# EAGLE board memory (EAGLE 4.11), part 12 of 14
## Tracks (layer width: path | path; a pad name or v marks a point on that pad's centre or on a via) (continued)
N$318  (via drill 0.61) (continued)
  Top 0.254: F14.S2 334.64,21.59 333.38,20.32 333.38,14.61 332.11,13.34 F14.V2 332.11,12.06 v332.11,9.52 | F09.P2 398.78,27.94 400.05,26.67 400.05,17.78 398.78,16.51 F09.U2 398.14,15.24 v398.14,9.52 400.69,6.98 400.69,1.27 460.38,1.27 v460.38,3.81 | v452.75,158.11 454.02,159.38 454.02,162.56 450.85,165.73 450.85,172.09 447.68,175.26 447.68,188.59 448.94,189.86 D05.E2 449.58,191.13 450.85,192.41 v450.85,211.45 | v446.4,147.32 447.04,146.69 447.04,134.62 447.68,133.99 447.68,90.8 v452.75,85.72 | v466.73,80.64 v466.73,54.61 466.73,45.72 472.44,45.72 473.07,45.09 473.07,42.55 469.9,39.37 469.9,10.16 v462.92,3.17 | v79.38,276.86 79.38,340.36 80.01,341 80.01,357.5 80.64,358.14 A34.U2 | v154.94,274.32 155.57,273.69 155.57,227.97 158.75,224.79 158.75,217.81 v164.47,212.09 | v223.52,215.26 v223.52,211.45
  Route2 0.254: v460.38,3.81 461.01,3.17 v462.92,3.17
  Bottom 0.254: F09.N2 395.61,31.12 397.51,29.21 398.14,29.21 F09.P2 | v332.11,9.52 370.84,9.52 371.48,10.16 397.51,10.16 v398.14,9.52 | v452.75,158.11 451.49,156.84 445.13,156.84 444.5,156.21 444.5,147.32 v446.4,147.32 | v452.75,85.72 457.83,80.64 v466.73,80.64 | v466.73,54.61 462.28,54.61 F04.E2 | v79.38,276.86 80.01,277.5 137.16,277.5 139.7,274.96 149.22,274.96 149.86,275.59 153.67,275.59 v154.94,274.32 | v164.47,212.09 165.1,212.72 175.26,212.72 175.9,213.36 205.1,213.36 207.01,211.45 v223.52,211.45 | v223.52,215.26 224.16,214.63 316.87,214.63 317.5,215.26 329.56,215.26 330.83,214 342.9,214 344.81,212.09 381,212.09 381.63,212.72 386.71,212.72 388.62,210.82 431.17,210.82 431.8,211.45 v450.85,211.45
N$319
  Route3 0.254: D05.D2 446.4,193.04 446.4,189.23 447.68,187.96 447.68,151.76 454.02,145.41 454.02,121.92 455.3,120.65 455.3,119.38 454.02,118.11 454.02,45.09 458.47,40.64 458.47,38.73 F04.L2
N$320
  Bottom 0.254: F09.M2 398.78,34.92 402.59,34.92 404.5,33.02 413.38,33.02 414.02,33.66 416.56,33.66 429.89,20.32 434.34,20.32 436.25,18.41 436.25,16.51 F06.U2
N$321
  Bottom 0.254: A12.S2 360.68,364.49 361.31,363.86 365.76,363.86 367.03,362.59 369.57,362.59 A11.T2
N$322  (via drill 0.61)
  Top 0.254: v439.42,189.23 441.32,191.13 441.32,206.38 439.42,208.28 439.42,217.17 438.15,218.44 438.15,227.33 439.42,228.6 v439.42,229.87 | v417.83,236.85 417.19,237.49 417.19,239.39 415.93,240.66 415.93,250.82 v417.19,252.09 | v414.65,313.06 413.38,314.33 413.38,316.23 412.75,316.87 412.75,324.49 414.02,325.75 v414.02,327.66 | v400.05,341.63 v405.13,336.55 | v373.38,342.27 373.38,358.14 A11.U2 | v273.05,417.2 273.05,398.78 271.78,397.51 A19.E2
  Route2 0.254: v405.13,336.55 v414.02,327.66
  Route3 0.254: v439.42,189.23 438.15,187.96 438.15,160.66 436.88,159.38 D06.S2 | v417.19,252.09 415.93,253.36 415.93,311.79 v414.65,313.06 | v365.76,415.29 365.12,414.66 365.12,403.86 361.95,400.69 361.95,386.08 374.65,373.38 374.65,360.68 373.38,359.41 A11.U2
  Bottom 0.254: v439.42,229.87 436.25,233.04 427.99,233.04 424.81,236.22 418.46,236.22 v417.83,236.85 | v400.05,341.63 387.99,341.63 387.35,342.27 v373.38,342.27 | v273.05,417.2 306.07,417.2 307.34,415.93 318.13,415.93 320.04,414.02 328.3,414.02 330.2,415.93 365.12,415.93 v365.76,415.29
N$323  (via drill 0.61)
  Top 0.254: v485.77,149.86 485.77,93.98 487.05,92.71 E02.S2
  Bottom 0.254: v485.77,149.86 485.14,150.5 478.79,150.5 474.35,154.94 471.81,154.94 D03.T2
N$326  (via drill 0.61)
  Top 0.254: v382.9,53.98 382.9,56.52 F10.D2
  Bottom 0.254: v382.9,53.98 384.18,55.25 386.71,55.25 389.89,52.07 392.43,52.07 393.06,52.7 401.95,52.7 402.59,52.07 411.48,52.07 415.29,55.88 417.83,55.88 418.46,55.25 427.36,55.25 427.99,55.88 430.53,55.88 431.17,55.25 440.06,55.25 440.69,55.88 443.23,55.88 443.87,55.25 452.75,55.25 453.39,55.88 455.93,55.88 456.56,55.25 465.45,55.25 466.09,55.88 468.63,55.88 469.26,55.25 473.71,55.25 474.35,54.61 F03.E2
N$327  (via drill 0.61)
  Top 0.254: v218.44,293.37 219.07,292.74 219.07,278.77 v224.16,273.69 | v274.32,271.78 274.95,272.42 274.95,278.13 v280.67,283.85 | v477.52,222.25 479.43,220.34 479.43,207.01 v480.06,206.38 | v494.03,109.22 492.76,107.95 492.76,106.04 492.12,105.41 492.12,50.16 v484.5,42.55
  Route2 0.254: v224.16,273.69 226.69,271.15 234.31,271.15 237.49,274.32 238.76,274.32 241.3,276.86 264.8,276.86 269.88,271.78 v274.32,271.78 | v280.67,283.85 281.94,282.58 287.65,282.58 288.93,283.85 311.15,283.85 313.69,281.31 320.04,281.31 321.94,283.21 367.03,283.21 367.67,283.85 368.3,283.85 369.57,282.58 392.43,282.58 394.33,284.48 396.24,284.48 396.88,285.12 400.05,285.12 408.94,276.23 417.83,276.23 434.98,259.08 441.96,259.08 442.6,258.44 448.31,258.44 v455.93,250.82 | v464.82,247.65 473.07,239.39 473.07,225.42 474.35,225.42 v477.52,222.25 | v480.06,206.38 494.67,191.77 501.01,191.77 501.65,191.13 501.65,187.32 500.38,186.06 500.38,185.42 501.01,185.42 501.65,184.78 501.65,131.44 502.92,131.44 504.19,130.18 504.19,128.91 502.92,128.91 495.3,121.28 495.3,109.22 v494.03,109.22
  Route3 0.254: v386.08,50.8 386.08,53.34 F10.E2
  Bottom 0.254: v386.08,50.8 386.08,48.9 387.35,48.9 390.52,45.72 400.69,45.72 401.32,46.36 403.86,46.36 405.13,45.09 407.67,45.09 F08.J2 408.31,45.09 410.21,46.99 410.85,46.99 F08.H2 411.48,46.99 412.12,46.36 416.56,46.36 417.19,45.72 426.08,45.72 426.72,46.36 429.26,46.36 433.07,42.55 441.96,42.55 442.6,43.18 451.49,43.18 452.12,42.55 454.66,42.55 455.3,43.18 464.19,43.18 464.82,42.55 467.36,42.55 468,43.18 476.25,43.18 480.69,38.73 | v218.44,293.37 214,293.37 213.36,294 208.91,294 208.28,294.64 B24.S2 | v455.93,250.82 457.2,252.09 460.38,252.09 v464.82,247.65 | 480.69,38.73 478.15,36.2 473.07,36.2 471.81,37.46 F03.L2 | 480.69,38.73 v484.5,42.55
N$328  (via drill 0.61)
  Top 0.254: v406.4,43.82 406.4,48.9 407.67,50.16 F08.F2
  Bottom 0.254: v406.4,43.82 407.04,43.18 413.38,43.18 414.02,42.55 416.56,42.55 417.19,43.18 426.08,43.18 426.72,42.55 429.26,42.55 429.89,43.18 431.17,43.18 432.44,41.91 436.25,41.91 F06.K2
N$329
  Bottom 0.254: E22.T2 230.5,88.27 232.41,86.36 233.04,86.36 E22.U2
N$330  (via drill 0.61)
  Top 0.254: B33.J2 90.17,318.14 90.17,323.22 B33.F2 | v209.55,320.68 v209.55,305.44
  Route2 0.254: v268.61,319.41 276.23,311.79 280.67,311.79 B18.L2 | B33.J2 90.81,316.87 90.81,313.06 99.06,313.06 105.41,306.71 111.76,306.71 115.57,302.9 124.46,302.9 128.27,306.71 137.16,306.71 140.97,302.9 147.32,302.9 150.5,299.72 157.48,299.72 161.29,303.53 172.09,303.53 172.72,302.9 175.26,302.9 179.07,306.71 187.96,306.71 188.59,306.07 197.49,306.07 198.12,306.71 200.66,306.71 201.93,305.44 204.47,305.44 B24.N2
  Bottom 0.254: v209.55,305.44 205.1,305.44 B24.N2 | v209.55,320.68 210.82,321.95 213.36,321.95 214,322.58 222.88,322.58 226.69,318.77 227.33,318.77 230.5,321.95 238.76,321.95 239.4,322.58 248.28,322.58 248.92,321.95 251.46,321.95 252.09,322.58 260.99,322.58 261.62,321.95 264.16,321.95 264.8,322.58 265.43,322.58 v268.61,319.41
N$331  (via drill 0.61)
  Top 0.254: v20.32,159.38 22.23,161.29 v22.23,180.34
  Bottom 0.254: v20.32,159.38 17.78,159.38 D39.S2 | v22.23,180.34 27.3,185.42 35.56,185.42 36.2,186.06 45.09,186.06 45.72,185.42 48.26,185.42 49.53,186.69 52.07,186.69 D36.F2
N$332
  Bottom 0.254: D39.N2 14.61,167.64 15.88,166.37 22.86,166.37 26.67,170.18 35.56,170.18 36.2,169.54 45.09,169.54 48.9,173.35 53.98,173.35 55.24,172.09 D36.M2
N$334  (via drill 0.61)
  Route3 0.254: v52.7,117.47 52.7,120.02 E36.F2
  Bottom 0.254: v52.7,117.47 55.24,117.47 E36.H2
OP1  (via drill 0.61)
  Top 0.254: v363.22,371.48 365.12,369.57 365.12,283.85 370.2,278.77 370.2,273.69 368.3,271.78 368.3,269.24 368.94,268.61 368.94,264.8 369.57,264.16 C11.D2 | B26.P2 182.88,302.26 183.51,302.9 183.51,306.71 184.15,307.34 184.15,325.12 182.88,326.39 B26.E2 | E13.R2 344.81,94.61 344.81,91.44 346.07,90.17 346.07,87.63 347.35,86.36 E13.U2 347.98,85.09 v347.98,73.02 | F17.K2 296.55,41.91 295.27,43.18 295.27,55.25 294,56.52 F17.D2 | v339.73,73.02 337.19,70.48 337.19,64.77 336.55,64.13 336.55,49.53 335.28,48.26 F14.H2 | v201.93,148.59 202.56,147.95 202.56,139.7 200.03,137.16 200.03,127.63 v205.1,122.55 | v368.3,237.49 368.3,220.98 363.22,215.9 363.22,201.93 361.95,200.66 361.95,189.23 v360.05,187.32
  Route2 0.254: v179.07,183.51 184.15,178.44 184.15,163.83 186.06,163.83 201.29,148.59 v201.93,148.59 | v205.1,122.55 206.38,121.28 206.38,116.2 211.46,116.2 217.81,109.85 226.06,109.85 229.87,106.04 234.31,106.04 238.12,102.23 238.12,95.25 v239.4,95.25 | v347.35,174.62 v360.05,187.32
  Route3 0.254: F14.D2 332.11,56.52 333.38,55.25 333.38,49.53 334.64,48.26 F14.H2 | v179.07,183.51 177.8,184.78 177.8,187.96 179.07,189.23 179.07,189.86 177.8,191.13 177.8,213.36 190.5,226.06 190.5,236.85 187.32,240.03 187.32,270.51 180.97,276.86 180.97,295.91 182.88,297.81 182.88,300.99 B26.P2 | v239.4,95.25 238.12,93.98 238.12,78.74 247.65,69.22 247.65,62.23 257.18,52.7 263.52,52.7 263.52,54.61 264.8,55.88 273.05,55.88 273.05,48.26 276.23,45.09 280.67,45.09 F18.J2 | v368.3,237.49 368.3,238.76 369.57,240.03 369.57,241.94 368.3,243.2 368.3,261.62 369.57,262.89 C11.D2 | v347.35,174.62 346.07,173.35 346.07,146.05 342.9,142.88 342.9,97.16 344.17,95.88 E13.R2
  Bottom 0.254: v363.22,371.48 360.68,371.48 A12.P2 | F18.J2 281.31,43.82 282.57,42.55 289.56,42.55 290.19,43.18 295.27,43.18 296.55,41.91 F17.K2 | F14.D2 331.47,57.15 327.66,57.15 325.75,59.05 316.87,59.05 316.23,58.42 313.69,58.42 313.06,59.05 304.17,59.05 303.53,58.42 300.99,58.42 300.36,59.05 295.27,59.05 294,57.79 F17.D2 | v347.98,73.02 v339.73,73.02
OP2  (via drill 0.61)
  Top 0.254: v282.57,3.81 282.57,26.03 281.31,27.3 281.31,31.12 F18.N2 | v396.88,3.17 396.88,20.32 398.14,21.59 F09.S2 | v320.68,280.67 320.68,286.39 319.4,287.66 319.4,291.47 B15.T2 | v252.09,281.94 248.92,281.94 v248.92,281.31 | v224.16,280.67 222.25,282.58 222.25,292.74 220.98,294 220.98,294.64 B23.S2 | v168.28,375.92 168.28,368.94 171.45,365.76 v171.45,361.95
  Route2 0.254: v248.92,281.31 247.65,282.58 226.06,282.58 v224.16,280.67 | v168.28,375.92 163.19,375.92 160.02,379.1 154.94,379.1 151.76,375.92 150.5,375.92 146.69,379.73 140.34,379.73 137.16,382.91 128.91,382.91 119.38,392.43 112.39,392.43 111.76,391.8 102.87,391.8 95.89,398.78 87,398.78 86.36,398.15 81.92,398.15 81.28,397.51 A34.E2 | v186.06,358.78 191.13,353.7 v227.33,353.7
  Route3 0.254: v227.33,353.7 228.6,352.43 228.6,320.04 225.43,316.87 225.43,296.55 v224.16,295.28 | v280.67,34.29 280.67,32.38 F18.N2 | v214.63,38.1 209.55,43.18 209.55,73.02 207.65,74.93 207.65,83.82 206.38,85.09 206.38,96.52 202.56,100.33 202.56,103.5 203.2,104.14 203.2,245.11 206.38,248.28 206.38,255.27 208.91,257.81 208.91,259.08 212.72,262.89 212.72,269.24 v224.16,280.67
  Bottom 0.254: v282.57,3.81 287.65,3.81 289.56,1.9 375.92,1.9 377.19,3.17 v396.88,3.17 | A35.F2 65.41,394.34 66.67,395.61 73.66,395.61 74.3,394.97 79.38,394.97 80.64,396.24 A34.E2 | v320.68,280.67 293.37,280.67 292.74,281.31 291.46,281.31 290.83,280.67 254.63,280.67 253.37,281.94 v252.09,281.94 | v171.45,361.95 171.45,360.05 175.26,360.05 175.9,360.68 179.07,360.68 179.71,360.05 184.15,360.05 185.42,358.78 v186.06,358.78 | v224.16,295.28 220.98,295.28 B23.S2 | v280.67,34.29 278.13,36.83 275.59,36.83 274.95,36.2 266.06,36.2 265.43,36.83 262.89,36.83 259.08,33.02 250.19,33.02 246.38,36.83 237.49,36.83 236.85,36.2 227.97,36.2 227.33,36.83 224.79,36.83 224.16,36.2 221.62,36.2 218.44,39.37 215.9,39.37 v214.63,38.1
OP+IOT  (via drill 0.61)
  Top 0.254: v350.52,34.92 350.52,34.29 349.25,33.02 349.25,24.13 347.98,22.86 F13.S2
  Route3 0.254: v350.52,34.92 352.43,36.83 352.43,70.48 351.15,71.75 351.15,77.47 352.43,78.74 352.43,100.96 355.6,104.14 v355.6,104.77
  Bottom 0.254: v355.6,104.77 356.87,106.04 365.76,106.04 370.2,110.49 372.75,110.49 E11.K2
OPR  (via drill 0.61)
  Top 0.254: v269.88,73.66 269.88,46.36 268.61,45.09 F19.J2 | v374.65,73.02 374.65,121.92 373.38,123.19 E11.E2 | v408.94,146.05 404.5,146.05 404.5,144.14 401.95,141.6 v401.95,139.7
  Route2 0.254: v484.5,203.84 v490.86,210.19 | v426.72,182.88 415.29,171.45 414.65,171.45 409.57,166.37 409.57,146.05 v408.94,146.05 | v401.95,139.7 400.05,137.79 395.61,137.79 392.43,134.62 389.89,134.62 389.25,135.25 386.71,135.25 v386.08,134.62
  Route3 0.254: v457.2,393.06 461.01,389.25 467.36,389.25 467.36,388.62 501.65,354.33 501.65,282.58 499.11,280.04 499.11,274.32 498.48,273.69 498.48,217.81 v490.86,210.19 | v386.08,134.62 384.81,133.35 384.81,131.44 382.9,129.54 382.9,127.63 E10.D2
  Bottom 0.254: v269.88,73.66 288.29,73.66 288.93,74.29 300.36,74.29 302.26,72.39 304.17,72.39 304.8,71.75 347.98,71.75 349.25,73.02 v374.65,73.02 | E10.D2 382.27,126.36 381.63,125.73 377.19,125.73 375.92,124.46 373.38,124.46 E11.E2 | v457.2,393.06 454.66,393.06 450.85,389.25 448.31,389.25 441.96,395.61 433.07,395.61 429.26,391.8 424.81,391.8 424.18,391.16 A07.H2 | v484.5,203.84 475.62,194.94 469.9,194.94 465.45,190.5 464.19,190.5 462.28,192.41 453.39,192.41 449.58,188.59 441.32,188.59 439.42,190.5 438.79,190.5 430.53,182.25 427.99,182.25 427.36,182.88 v426.72,182.88
PB  (via drill 0.61)
  Top 0.254: 438.15,30.48 436.88,29.21 F06.P2 | 438.15,45.72 438.15,30.48 | 438.15,45.72 436.88,46.99 F06.H2 | v436.25,109.22 438.15,107.31 | 438.15,107.31 438.15,45.72 | 438.15,107.31 438.15,137.16 437.51,137.79 437.51,147.95 438.15,148.59 438.15,165.73 437.51,166.37 437.51,170.18 436.88,170.81 D06.M2 | 440.69,10.79 438.15,10.79 438.15,30.48 | 440.69,10.79 446.4,10.79 447.68,12.06 447.68,13.34 447.04,13.97 447.04,17.78 446.4,18.41 F05.T2 | v55.88,4.44 55.88,15.24 F36.U2 | v377.82,44.45 v377.82,5.71 v377.82,1.27 | 440.69,10.79 v440.69,9.52
  Bottom 0.254: v436.25,109.22 429.89,109.22 429.26,109.85 424.81,109.85 424.18,110.49 E07.K2 | v55.88,4.44 59.05,1.27 196.85,1.27 198.75,3.17 200.66,3.17 201.29,2.54 221.62,2.54 222.25,3.17 224.16,1.27 284.48,1.27 285.75,2.54 286.38,2.54 288.29,0.63 377.19,0.63 v377.82,1.27 | v377.82,44.45 379.1,45.72 384.18,45.72 385.44,46.99 F10.H2 | v440.69,9.52 437.51,6.35 410.21,6.35 409.57,5.71 395.61,5.71 394.97,5.08 378.46,5.08 v377.82,5.71
PC11  (via drill 0.61)
  Top 0.254: v262.25,234.95 263.52,236.22 263.52,242.57 v265.43,244.47 | v347.98,113.03 347.98,116.84 E13.H2 | v402.59,145.41 406.4,149.22 406.4,153.67 407.67,154.94 D08.T2 | v390.52,222.25 v390.52,214 | v400.05,214 v400.05,195.58 | 187.32,377.19 187.32,357.5 190.5,354.33 190.5,332.11 191.77,330.84 B25.D2 192.41,329.56 v192.41,325.75 | 187.32,377.19 180.97,383.54 v180.97,386.72 | v425.45,419.1 425.45,386.08 424.18,384.81 A07.K2 | 187.32,377.19 v187.32,419.74 | v215.9,246.38 215.9,283.21 v214,285.12
  Route2 0.254: v262.25,234.95 263.52,233.68 263.52,231.14 262.25,229.87 259.71,229.87 259.08,229.23 C20.S2 | v347.98,113.03 341,113.03 337.82,109.85 333.38,109.85 332.11,108.58 E14.L2 | v214,285.12 211.46,287.66 205.1,287.66 v203.2,289.56
  Route3 0.254: D08.T2 407.67,156.21 406.4,157.48 406.4,187.96 407.04,188.59 407.04,192.41 407.67,193.04 D08.D2 | v353.69,120.65 354.96,121.92 354.96,122.55 355.6,123.19 355.6,138.43 357.5,140.34 v357.5,145.41 | v337.82,242.57 342.26,238.12 342.26,236.22 342.9,235.59 342.9,224.79 v344.17,223.52 | v203.2,289.56 200.03,292.74 200.03,320.04 v196.85,323.22
  Bottom 0.254: v353.69,120.65 351.79,118.74 348.62,118.74 347.98,118.11 E13.H2 | v357.5,145.41 358.14,146.05 398.14,146.05 398.78,145.41 v402.59,145.41 | v337.82,242.57 333.38,242.57 332.11,243.84 C14.L2 331.47,243.84 328.93,243.84 327.66,242.57 325.12,242.57 324.49,243.2 315.6,243.2 314.96,242.57 309.25,242.57 308.61,243.2 302.89,243.2 302.26,242.57 293.37,242.57 292.1,243.84 289.56,243.84 288.29,242.57 287.02,242.57 286.38,243.2 277.5,243.2 276.86,242.57 267.33,242.57 v265.43,244.47 264.8,245.11 263.52,245.11 262.25,246.38 253.37,246.38 249.56,242.57 247.01,242.57 243.84,245.75 237.49,245.75 236.85,246.38 227.97,246.38 227.33,245.75 224.79,245.75 224.16,246.38 v215.9,246.38 | v344.17,223.52 353.06,223.52 353.69,224.16 362.58,224.16 363.22,223.52 365.76,223.52 366.39,224.16 375.29,224.16 375.92,223.52 378.46,223.52 379.1,224.16 379.73,224.16 382.9,220.98 387.35,220.98 387.99,221.61 389.89,221.61 v390.52,222.25 | v390.52,214 v400.05,214 | v400.05,195.58 402.59,195.58 404.5,193.67 407.67,193.67 D08.D2 | v180.97,386.72 180.97,388.62 175.26,388.62 173.99,389.89 170.18,389.89 A27.H2 | v425.45,419.1 415.93,419.1 414.65,420.37 313.06,420.37 311.79,419.1 310.51,419.1 308.61,421 268.61,421 266.7,419.1 265.43,420.37 187.96,420.37 v187.32,419.74 | v196.85,323.22 194.31,325.75 v192.41,325.75
PE  (via drill 0.61)
  Top 0.254: v422.27,91.44 422.27,111.76 423.55,113.03 423.55,116.84 E07.H2 | v273.69,277.5 v273.69,284.48 | v304.8,270.51 304.8,240.03 303.53,238.76 v303.53,236.85 | v307.34,236.22 304.8,233.68 v304.8,186.69
  Route2 0.254: v217.17,358.78 212.09,363.86 208.91,363.86 208.28,364.49 A24.S2 | v252.09,297.18 250.82,295.91 250.82,294 v255.91,288.93 | v273.69,277.5 276.23,274.96 279.4,274.96 284.48,269.88 285.12,269.88 287.02,271.78 289.56,271.78 290.19,271.15 299.08,271.15 299.72,271.78 302.26,271.78 303.53,270.51 v304.8,270.51 | v304.8,186.69 306.07,185.42 310.51,185.42 320.68,175.26 320.68,173.35 314.32,167 314.32,163.83 314.96,163.83 315.6,163.19 316.87,163.19 v328.93,175.26 | v363.86,176.53 367.67,172.72 375.29,172.72 393.7,154.31 393.7,141.6 401.95,141.6 406.4,137.16 406.4,122.55 416.56,122.55 421,118.11 423.55,118.11 E07.H2
  Route3 0.254: v240.03,354.33 241.3,353.06 241.3,322.58 v243.21,320.68 | v252.09,318.14 254,316.23 254,299.09 v252.09,297.18
  Bottom 0.254: v422.27,91.44 422.91,90.8 429.26,90.8 430.53,89.53 433.07,89.53 E06.T2 | v217.17,358.78 218.44,357.5 221.62,357.5 222.25,358.14 225.43,358.14 226.69,356.87 231.14,356.87 231.78,357.5 236.85,357.5 v240.03,354.33 | v243.21,320.68 244.47,319.41 250.82,319.41 v252.09,318.14 | v255.91,288.93 257.18,287.66 262.25,287.66 265.43,284.48 v273.69,284.48 | v303.53,236.85 304.17,236.22 v307.34,236.22 | v328.93,175.26 330.2,176.53 338.45,176.53 341,173.99 341.63,173.99 344.17,176.53 353.06,176.53 353.69,175.89 355.6,175.89 357.5,177.8 358.14,177.8 359.41,176.53 v363.86,176.53
PE_SEL  (via drill 0.61)
  Route2 0.254: v313.69,384.81 313.06,384.18 311.79,384.18 309.88,386.08 302.26,386.08 300.36,384.18 299.08,384.18 294.64,388.62 288.29,388.62 287.65,389.25 281.31,389.25 v280.67,389.89 | v223.52,384.18 221.62,382.27 214.63,382.27 207.65,375.29 205.1,375.29 A24.N2 | v411.48,45.09 417.19,39.37 419.74,39.37 420.37,38.73 F07.L2 | v396.88,116.84 393.7,120.02 393.7,127.63 390.52,127.63 v382.9,135.25 | v379.1,155.57 378.46,156.21 377.82,156.21 v360.05,173.99
  Route3 0.254: v360.05,345.44 358.77,344.17 358.77,331.47 361.95,328.3 361.95,314.96 368.3,308.61 368.3,290.83 371.48,287.66 371.48,285.12 374.65,281.94 374.65,266.06 370.84,262.25 370.84,258.44 370.2,257.81 C11.F2 | v331.47,345.44 331.47,353.7 327.02,358.14 327.02,375.29 316.23,386.08 313.69,386.08 v313.69,384.81 | v411.48,45.09 403.23,53.34 403.23,75.56 400.05,78.74 400.05,99.06 394.33,104.77 396.88,107.31 396.88,114.3 398.14,115.57 v396.88,116.84 | v382.9,135.25 382.27,135.89 382.27,142.24 381,143.51 381,153.67 v379.1,155.57 | v360.05,173.99 358.77,175.26 358.77,182.25 355.6,185.42 v355.6,240.66 | v360.68,243.84 365.12,248.28 365.12,255.27 v367.03,257.18
  Bottom 0.254: v360.05,345.44 359.41,344.81 340.36,344.81 339.73,345.44 v331.47,345.44 | v280.67,389.89 277.5,386.72 276.23,386.72 274.95,385.45 266.06,385.45 265.43,386.08 262.89,386.08 262.25,385.45 253.37,385.45 252.73,386.08 250.19,386.08 249.56,385.45 240.66,385.45 240.03,386.08 237.49,386.08 236.85,385.45 227.97,385.45 227.33,386.08 226.06,386.08 224.16,384.18 v223.52,384.18 | v355.6,240.66 358.77,243.84 v360.68,243.84 | v367.03,257.18 369.57,257.18 C11.F2
PIR  (via drill 0.61)
  Top 0.254: v138.43,161.29 136.53,163.19 v136.53,170.81
  Route2 0.254: v189.87,147.32 v173.35,163.83 | v167,320.04 168.91,321.95 173.35,321.95 178.44,327.03 180.34,327.03 181.61,325.75 184.78,325.75 186.06,327.03 186.69,327.03 191.13,322.58 194.31,322.58 198.75,327.03 199.39,327.03 201.29,325.12 208.28,325.12 v209.55,326.39 | v240.03,387.35 241.94,389.25 248.92,389.25 252.09,392.43 260.99,392.43 261.62,391.8 264.16,391.8 264.8,392.43 273.69,392.43 274.32,391.8 276.86,391.8 277.5,392.43 286.38,392.43 287.02,391.8 289.56,391.8 290.19,392.43 291.46,392.43 292.1,391.8 302.26,391.8 302.89,392.43 311.79,392.43 312.42,391.8 314.96,391.8 318.77,395.61 327.66,395.61 331.47,391.8 340.36,391.8 344.17,395.61 353.06,395.61 353.69,394.97 360.05,394.97 366.39,388.62 v372.11,388.62
  Route3 0.254: v208.28,44.45 203.2,49.53 203.2,76.83 200.03,80.01 200.03,96.52 193.68,102.87 193.68,143.51 v189.87,147.32 | v136.53,170.81 135.25,172.09 135.25,172.72 136.53,173.99 136.53,192.41 137.79,193.67 137.79,194.94 136.53,196.22 136.53,224.16 137.79,225.42 137.79,226.69 136.53,227.97 136.53,237.49 139.7,240.66 139.7,271.78 152.4,284.48 152.4,294.64 161.93,304.17 161.93,309.25 166.37,313.69 166.37,315.6 165.1,316.87 165.1,318.14 v167,320.04 | v209.55,326.39 210.82,326.39 211.46,325.75 212.72,325.75 212.72,328.3 222.25,337.82 222.25,351.79 234.95,364.49 234.95,382.27 v240.03,387.35 | v372.11,388.62 381,379.73 381,363.86 382.27,362.59 A10.T2
  Bottom 0.254: v208.28,44.45 210.19,42.55 211.46,42.55 212.09,43.18 216.53,43.18 217.17,43.82 F23.J2 | v173.35,163.83 164.47,163.83 163.83,163.19 161.29,163.19 160.66,163.83 152.4,163.83 146.05,157.48 142.24,157.48 v138.43,161.29
PT  (via drill 0.61)
  Top 0.254: v422.27,116.2 422.27,153.67 421,154.94 D07.T2
  Bottom 0.254: v422.27,116.2 427.36,116.2 427.99,115.57 432.44,115.57 433.07,114.93 E06.J2
RAMA00\
  Bottom 0.254: D28.D2 154.31,194.31 155.57,195.58 162.56,195.58 163.19,194.94 172.09,194.94 172.72,195.58 175.26,195.58 175.9,194.94 184.78,194.94 185.42,195.58 187.96,195.58 188.59,194.94 197.49,194.94 198.12,195.58 200.66,195.58 201.29,194.94 210.19,194.94 210.82,195.58 213.36,195.58 214,194.94 222.88,194.94 223.52,195.58 226.06,195.58 226.69,194.94 235.59,194.94 236.22,195.58 237.49,195.58 239.4,193.67 242.57,193.67 D21.D2
RAMA01\  (via drill 0.61)
  Route3 0.254: v157.48,186.06 157.48,189.86 D28.E2
  Bottom 0.254: v157.48,186.06 161.29,182.25 172.09,182.25 172.72,182.88 175.26,182.88 175.9,182.25 184.78,182.25 185.42,182.88 187.96,182.88 188.59,182.25 197.49,182.25 198.12,182.88 200.66,182.88 201.29,182.25 210.19,182.25 210.82,182.88 213.36,182.88 214,182.25 222.88,182.25 226.69,186.06 235.59,186.06 236.22,185.42 237.49,185.42 238.76,186.69 242.57,186.69 D21.F2
RAMA02\  (via drill 0.61)
  Top 0.254: v155.57,204.47 155.57,193.04 154.31,191.77 154.31,187.96 D28.F2 | v214.63,207.64 215.9,206.38 215.9,186.69 v217.81,184.78
  Route2 0.254: v217.81,184.78 219.71,182.88 226.06,182.88 226.69,182.25 235.59,182.25 236.22,182.88 238.76,182.88 240.03,181.61 242.57,181.61 D21.J2
  Bottom 0.254: v155.57,204.47 156.21,205.1 161.93,205.1 163.19,206.38 184.78,206.38 186.69,208.28 214,208.28 v214.63,207.64
RAMA03\  (via drill 0.61)
  Route2 0.254: v166.37,178.44 161.93,182.88 158.12,182.88 157.48,183.51 D28.H2
  Bottom 0.254: v166.37,178.44 168.28,176.53 175.26,176.53 175.9,175.89 184.78,175.89 185.42,176.53 187.96,176.53 188.59,175.89 197.49,175.89 198.12,176.53 200.66,176.53 201.29,175.89 210.19,175.89 210.82,176.53 213.36,176.53 214,175.89 222.88,175.89 223.52,176.53 226.06,176.53 226.69,175.89 235.59,175.89 236.22,176.53 237.49,176.53 238.76,175.26 242.57,175.26 D21.L2
RAMA04\  (via drill 0.61)
  Top 0.254: v152.4,161.29 152.4,175.26 153.03,175.89 153.03,179.7 153.67,180.34 D28.J2
  Route3 0.254: v152.4,161.29 155.57,158.11 v155.57,146.05 | v239.4,147.32 241.3,149.22 241.3,166.37 242.57,167.64 D21.N2
  Bottom 0.254: v155.57,146.05 156.84,144.78 196.85,144.78 199.39,147.32 213.36,147.32 216.53,150.5 218.44,150.5 221.62,147.32 v239.4,147.32
RAMA05\
  Bottom 0.254: D28.K2 156.84,177.16 156.21,176.53 153.67,176.53 152.4,175.26 152.4,172.72 162.56,172.72 163.19,173.35 172.09,173.35 172.72,172.72 175.26,172.72 175.9,173.35 184.78,173.35 191.77,166.37 198.75,166.37 202.56,170.18 213.36,170.18 214,169.54 222.88,169.54 223.52,170.18 226.06,170.18 226.69,169.54 233.04,169.54 240.03,162.56 242.57,162.56 D21.R2
RAMA06\  (via drill 0.61)
  Top 0.254: v175.9,180.97 177.8,182.88 v177.8,189.86
  Bottom 0.254: v175.9,180.97 173.99,179.07 172.72,179.07 172.09,179.7 163.19,179.7 161.93,178.44 160.66,178.44 158.12,175.89 154.94,175.89 154.31,175.26 D28.L2 | v177.8,189.86 179.71,191.77 187.96,191.77 188.59,192.41 197.49,192.41 198.12,191.77 200.66,191.77 201.29,192.41 210.19,192.41 210.82,191.77 213.36,191.77 214,192.41 222.88,192.41 223.52,191.77 226.06,191.77 227.33,193.04 229.87,193.04 D22.D2
RAMA07\  (via drill 0.61)
  Route2 0.254: v171.45,183.51 171.45,182.25 161.93,172.72 158.12,172.72 157.48,172.09 D28.M2
  Bottom 0.254: v171.45,183.51 173.99,186.06 184.78,186.06 185.42,185.42 187.96,185.42 188.59,186.06 197.49,186.06 198.12,185.42 200.66,185.42 201.29,186.06 210.19,186.06 210.82,185.42 213.36,185.42 214,186.06 222.88,186.06 223.52,185.42 224.79,185.42 226.06,186.69 229.87,186.69 D22.F2
RAMA08\  (via drill 0.61)
  Route3 0.254: v179.07,172.09 177.8,173.35 v177.8,177.16
  Bottom 0.254: v179.07,172.09 176.53,169.54 175.9,169.54 175.26,170.18 172.72,170.18 172.09,169.54 163.19,169.54 162.56,170.18 155.57,170.18 154.31,168.91 D28.N2 | v177.8,177.16 179.71,179.07 187.96,179.07 188.59,179.7 197.49,179.7 198.12,179.07 200.66,179.07 201.29,179.7 210.19,179.7 210.82,179.07 213.36,179.07 214,179.7 222.88,179.7 223.52,179.07 226.06,179.07 227.33,180.34 229.87,180.34 D22.J2
RAMA09\  (via drill 0.61)
  Top 0.254: v185.42,166.37 187.32,166.37 v187.32,173.35
  Bottom 0.254: v185.42,166.37 180.34,166.37 177.16,163.19 175.9,163.19 172.09,167 163.19,167 162.56,166.37 158.12,166.37 157.48,165.73 D28.P2 | v187.32,173.35 197.49,173.35 198.12,172.72 200.66,172.72 201.29,173.35 210.19,173.35 210.82,172.72 213.36,172.72 214,173.35 222.88,173.35 223.52,172.72 226.06,172.72 227.33,173.99 229.87,173.99 D22.L2
RAMA10\  (via drill 0.61)
  Top 0.254: v152.4,146.05 152.4,160.02 153.67,161.29 D28.R2 | v215.26,147.95 215.9,148.59 v215.9,164.47
  Bottom 0.254: v152.4,146.05 154.31,144.14 197.49,144.14 200.03,146.69 214,146.69 v215.26,147.95 | v215.9,164.47 217.81,166.37 226.06,166.37 227.33,167.64 229.87,167.64 D22.N2
RAMA11\
  Bottom 0.254: D28.S2 157.48,159.38 158.12,160.02 162.56,160.02 163.19,160.66 172.09,160.66 172.72,160.02 175.26,160.02 175.9,160.66 184.78,160.66 185.42,160.02 187.96,160.02 188.59,160.66 197.49,160.66 198.12,160.02 200.66,160.02 201.29,160.66 210.19,160.66 210.82,160.02 213.36,160.02 214,160.66 222.88,160.66 223.52,160.02 226.06,160.02 227.33,161.29 229.87,161.29 D22.R2
RAMA12\  (via drill 0.61)
  Top 0.254: v155.57,191.77 155.57,161.29 154.94,160.66 154.94,156.84 154.31,156.21 D28.T2
  Bottom 0.254: v155.57,191.77 161.93,191.77 163.83,193.67 166.37,193.67 D27.D2
RAMA13\  (via drill 0.61)
  Top 0.254: v161.93,187.32 161.93,161.29 158.75,158.11 158.75,154.31 157.48,153.03 D28.U2
  Bottom 0.254: v161.93,187.32 166.37,187.32 D27.F2
RAMA14\  (via drill 0.61)
  Top 0.254: v158.75,177.8 158.75,163.19 155.57,160.02 155.57,151.13 154.31,149.86 D28.V2
  Bottom 0.254: v158.75,177.8 160.02,179.07 161.29,179.07 162.56,180.34 166.37,180.34 D27.J2
RAMD00  (via drill 0.61)
  Route3 0.254: v225.43,262.25 224.16,260.99 220.98,260.99 C23.E2
  Bottom 0.254: v225.43,262.25 226.06,262.89 226.69,262.89 | 226.69,262.89 229.87,262.89 C22.D2 | 226.69,262.89 224.16,265.43 223.52,265.43 222.88,264.8 214,264.8 213.36,265.43 202.56,265.43 201.93,264.8 201.29,264.8 200.66,265.43 198.12,265.43 197.49,264.8 188.59,264.8 187.96,265.43 185.42,265.43 184.78,264.8 175.9,264.8 175.26,265.43 172.72,265.43 172.09,264.8 163.19,264.8 162.56,265.43 155.57,265.43 154.31,264.16 C28.D2
RAMD01  (via drill 0.61)
  Top 0.254: v225.43,253.36 226.69,252.09 229.87,252.09 229.87,256.54 C22.F2
  Bottom 0.254: C28.E2 157.48,259.72 158.12,259.08 162.56,259.08 163.19,258.44 172.09,258.44 172.72,259.08 175.26,259.08 175.9,258.44 184.78,258.44 185.42,259.08 187.96,259.08 188.59,258.44 197.49,258.44 198.12,259.08 200.66,259.08 201.29,258.44 210.19,258.44 210.82,259.08 213.36,259.08 214,258.44 222.88,258.44 223.52,259.08 226.06,259.08 227.33,257.81 229.87,257.81 C22.F2 | v225.43,253.36 220.98,253.36 C23.H2
RAMD02  (via drill 0.61)
  Top 0.254: v218.44,252.09 220.34,250.19 220.34,248.28 C23.K2
  Route3 0.254: v154.31,252.73 154.31,256.54 C28.F2
  Bottom 0.254: v154.31,252.73 162.56,252.73 163.19,252.09 172.09,252.09 172.72,252.73 175.26,252.73 175.9,252.09 184.78,252.09 185.42,252.73 187.96,252.73 188.59,252.09 197.49,252.09 198.12,252.73 200.66,252.73 201.29,252.09 210.19,252.09 210.82,252.73 213.36,252.73 214,252.09 v218.44,252.09 | C22.J2 229.87,250.19 229.24,249.56 224.79,249.56 223.52,248.28 220.98,248.28 C23.K2
RAMD03
  Bottom 0.254: C28.H2 156.84,254 154.31,254 152.4,252.09 152.4,241.3 154.94,241.3 156.21,242.57 162.56,242.57 163.19,243.2 169.54,243.2 170.18,242.57 175.26,242.57 175.9,243.2 177.16,243.2 177.8,242.57 187.96,242.57 188.59,243.2 197.49,243.2 198.12,242.57 200.66,242.57 201.29,243.2 210.19,243.2 210.82,242.57 213.36,242.57 214,243.2 219.07,243.2 220.34,241.94 C23.M2 220.98,241.94 223.52,241.94 224.79,243.2 229.24,243.2 229.87,243.84 C22.L2
RAMD04  (via drill 0.61)
  Route3 0.254: v158.75,241.3 158.75,245.11 166.37,252.73 166.37,255.91 163.19,255.91 158.75,251.46 154.31,251.46 C28.J2
  Bottom 0.254: v158.75,241.3 160.02,240.03 162.56,240.03 163.19,239.39 172.09,239.39 172.72,240.03 175.26,240.03 175.9,239.39 184.78,239.39 185.42,240.03 187.96,240.03 188.59,239.39 197.49,239.39 198.12,240.03 200.66,240.03 201.29,239.39 210.19,239.39 210.82,240.03 213.36,240.03 214,239.39 218.44,239.39 220.34,237.49 220.34,235.59 C23.P2 220.98,235.59 223.52,235.59 225.43,237.49 229.87,237.49 C22.N2
RAMD05  (via drill 0.61)
  Top 0.254: v171.45,216.53 v171.45,245.75 | v222.25,215.9 222.25,223.52 220.98,224.79 220.98,227.97 C23.S2
  Route3 0.254: v223.52,228.6 v226.06,231.14
  Bottom 0.254: v171.45,245.75 163.19,245.75 162.56,246.38 158.12,246.38 157.48,247.01 C28.K2 | v171.45,216.53 221.62,216.53 v222.25,215.9 | v226.06,231.14 229.87,231.14 C22.R2 | v223.52,228.6 220.98,228.6 C23.S2
RAMD06  (via drill 0.61)
  Top 0.254: v175.9,250.19 177.8,252.09 177.8,259.72 179.07,260.99 182.25,260.99 C26.E2
  Bottom 0.254: v175.9,250.19 174.62,248.92 172.72,248.92 172.09,249.56 163.19,249.56 162.56,248.92 154.31,248.92 154.31,245.11 C28.L2 | C25.D2 191.77,262.89 187.32,262.89 185.42,260.99 182.88,260.99 C26.E2
RAMD07  (via drill 0.61)
  Top 0.254: v162.56,238.76 161.29,240.03 160.02,240.03 158.75,238.76 157.48,240.03 157.48,240.66 C28.M2 | v184.15,236.85 184.15,252.09 182.88,253.36 C26.H2 182.25,254.63 182.25,259.08 186.06,259.08 189.87,255.27 190.5,255.27 191.77,256.54 C25.F2
  Bottom 0.254: v162.56,238.76 165.1,236.22 175.26,236.22 175.9,236.85 v184.15,236.85
RAMD08  (via drill 0.61)
  Route3 0.254: v157.48,238.12 158.75,238.12 158.75,238.76 165.74,245.75 v165.74,247.01
  Bottom 0.254: v157.48,238.12 154.31,238.12 C28.N2 | v165.74,247.01 166.37,246.38 170.81,246.38 171.45,247.01 174.62,247.01 175.9,245.75 180.97,245.75 182.25,247.01 C26.K2 182.88,248.28 185.42,248.28 186.69,249.56 191.13,249.56 191.77,250.19 C25.J2
RAMD09  (via drill 0.61)
  Top 0.254: v182.25,245.75 182.25,241.94 C26.M2 182.88,240.66 182.88,236.85 184.15,235.59 185.42,235.59 187.32,237.49 187.32,249.56 189.23,249.56 191.77,247.01 191.77,245.11 C25.L2
  Route2 0.254: v182.25,245.75 174.62,245.75 174.62,243.84 173.35,242.57 168.91,242.57 167,240.66 166.37,240.66 163.83,243.2 163.19,243.2 162.56,242.57 155.57,242.57 155.57,238.76 156.84,237.49 156.84,235.59 C28.P2
RAMD10  (via drill 0.61)
  Top 0.254: v156.84,225.42 154.94,227.33 154.94,230.5 154.31,231.14 C28.R2 | v184.15,224.16 184.15,233.04 182.88,234.31 C26.P2
  Bottom 0.254: v156.84,225.42 158.75,223.52 162.56,223.52 163.19,224.16 172.09,224.16 172.72,223.52 175.26,223.52 175.9,224.16 v184.15,224.16 | C25.N2 191.77,237.49 191.13,236.85 186.69,236.85 185.42,235.59 182.88,235.59 C26.P2
RAMD11
  Route2 0.254: C25.R2 191.77,231.14 191.13,230.5 186.69,230.5 185.42,229.23 182.88,229.23 C26.S2
  Bottom 0.254: C28.S2 157.48,227.97 161.93,227.97 163.19,226.69 163.83,226.69 164.47,227.33 175.26,227.33 175.9,226.69 179.71,226.69 181.61,228.6 182.25,228.6 C26.S2
RAMD12  (via drill 0.61)
  Top 0.254: v168.28,221.61 168.28,261.62 167,262.89 C27.D2
  Bottom 0.254: 168.28,220.34 172.09,220.34 172.72,220.98 175.26,220.98 175.9,220.34 180.34,220.34 181.61,221.61 182.25,221.61 C26.U2 | 168.28,220.34 163.19,220.34 162.56,220.98 154.31,220.98 154.31,224.79 C28.T2 | 168.28,220.34 v168.28,221.61
RD\  (via drill 0.61)
  Top 0.254: v161.29,212.72 165.1,208.91 165.1,170.18 166.37,168.91 D27.N2 | v157.48,212.72 154.31,215.9 154.31,218.44 C28.V2
  Bottom 0.254: v161.29,212.72 v157.48,212.72
RD_RQ  (via drill 0.61)
  Top 0.254: 107.95,125.09 107.95,150.5 106.68,151.76 D32.U2 | 107.95,125.09 107.95,24.13 106.68,22.86 F32.S2 | v109.86,125.09 107.95,125.09
  Bottom 0.254: v109.86,125.09 110.49,125.73 113.03,125.73 113.67,125.09 122.56,125.09 123.19,125.73 125.73,125.73 126.36,125.09 135.25,125.09 135.89,125.73 140.34,125.73 140.97,126.36 E29.D2
READ  (via drill 0.61)
  Top 0.254: v136.53,172.09 v136.53,193.67 | v118.11,170.18 117.47,169.54 117.47,159.38 114.3,156.21 v114.3,59.69
  Bottom 0.254: 114.3,58.42 116.84,58.42 118.75,56.52 118.75,54.61 F31.E2 | 114.3,58.42 112.39,58.42 111.76,59.05 104.78,59.05 103.5,57.79 F32.D2 | v136.53,193.67 140.97,193.67 D29.D2 | v136.53,172.09 133.99,169.54 123.19,169.54 122.56,170.18 v118.11,170.18 | v114.3,59.69 114.3,58.42
RIMA  (via drill 0.61)
  Top 0.254: v167,247.65 161.93,252.73 161.93,284.48 166.37,288.93 v166.37,289.56
  Route2 0.254: v176.53,149.22 187.32,138.43 195.58,138.43 199.39,134.62 207.01,134.62 213.36,128.27 218.44,128.27 227.97,118.74 236.85,118.74 237.49,119.38 240.03,119.38 240.66,118.74 249.56,118.74 250.19,119.38 254,119.38 260.99,112.39 262.25,112.39 262.89,113.03 265.43,113.03 266.06,112.39 274.95,112.39 275.59,113.03 281.94,113.03 285.12,116.2 287.65,116.2 288.29,115.57 290.83,115.57 291.46,116.2 300.36,116.2 300.99,115.57 307.34,115.57 313.69,109.22 318.13,109.22 318.77,108.58 E15.L2 | v176.53,323.85 178.44,321.95 187.96,321.95 188.59,322.58 189.87,322.58 190.5,321.95 200.66,321.95 201.29,322.58 207.01,322.58 v211.46,327.03 | v228.6,381 228.6,382.91 238.76,382.91 239.4,382.27 248.28,382.27 248.92,382.91 251.46,382.91 252.09,382.27 260.99,382.27 264.8,386.08 266.06,386.08 269.24,382.91 276.86,382.91 278.13,381.64 280.67,381.64 A18.L2
  Route3 0.254: v176.53,149.22 175.26,150.5 175.26,151.13 168.28,158.11 168.28,187.96 165.1,191.13 165.1,211.45 165.74,212.09 165.74,217.81 165.1,218.44 165.1,234.31 168.28,237.49 168.28,246.38 v167,247.65 | v166.37,289.56 174.62,297.81 174.62,321.95 v176.53,323.85 | v211.46,327.03 212.09,327.66 212.09,328.93 215.9,332.74 215.9,363.86 228.6,376.56 v228.6,381
RIPC  (via drill 0.61)
  Top 0.254: v282.57,209.55 282.57,193.04 281.31,191.77 281.31,187.96 D18.F2 | v311.15,209.55 311.15,232.41 313.06,234.31 v313.06,234.95 | v318.77,240.03 318.77,243.84 C15.L2
  Bottom 0.254: v282.57,209.55 283.21,210.19 310.51,210.19 v311.15,209.55 | v313.06,234.95 314.96,236.85 320.04,236.85 320.68,237.49 320.68,240.03 v318.77,240.03
ROTR  (via drill 0.61)
  Top 0.254: v147.32,160.02 148.59,158.75 148.59,156.84 149.22,156.21 149.22,149.86 151.13,147.95 151.13,140.34 v154.31,137.16
  Route2 0.254: v146.05,344.17 147.32,345.44 162.56,345.44 168.28,351.16 172.09,351.16 174.62,353.7 182.25,353.7 182.25,358.14 A26.U2 | v154.31,137.16 179.07,112.39 186.69,112.39 v188.59,114.3
  Route3 0.254: v146.05,344.17 146.05,283.85 133.35,271.15 133.35,215.9 v135.25,214 | v137.79,214 141.6,210.19 141.6,201.93 142.88,200.66 142.88,177.16 v144.15,175.89 | v188.59,114.3 190.5,112.39 190.5,99.06 193.68,95.88 193.68,80.64 201.29,73.02 201.29,68.58 200.03,67.31 200.03,46.36 217.81,28.58 217.81,27.94 225.43,20.32 235.59,20.32 v237.49,22.23
  Bottom 0.254: v135.25,214 v137.79,214 | v144.15,175.89 147.32,172.72 147.32,170.18 146.05,168.91 146.05,160.02 v147.32,160.02 | v237.49,22.23 241.94,26.67 248.28,26.67 248.92,27.3 251.46,27.3 255.27,23.49 263.52,23.49 265.43,25.4 267.97,25.4 F19.R2
ROTR+ROTL+TAD  (via drill 0.61)
  Top 0.254: F17.V2 294,13.34 296.55,15.88 F17.U2 | v242.57,365.12 238.76,361.31 238.76,360.05 238.12,359.41 v238.12,320.68 | v230.5,315.6 228.6,313.69 228.6,302.26 231.78,299.09 v231.78,288.93 | v211.46,273.69 209.55,271.78 209.55,257.81 203.2,251.46 203.2,132.72 v204.47,131.44 | v232.41,59.05 231.78,58.42 231.78,46.99 236.85,41.91 v236.85,40.01 | v403.23,10.16 403.23,29.21 409.57,35.56 409.57,52.07 410.85,53.34 F08.E2 | v372.75,12.06 372.75,8.89 367.67,3.81 340.36,3.81 340.36,12.7 342.9,15.24 342.9,23.49 v341,25.4
  Route2 0.254: v242.57,365.12 245.75,365.12 A21.S2 | v208.28,95.88 219.71,84.45 226.06,84.45 226.69,83.82 v233.04,83.82 | v403.23,10.16 402.59,10.79 374.01,10.79 v372.75,12.06 | v341,25.4 339.09,27.3 333.38,27.3 332.11,26.03 F14.R2
  Route3 0.254: v328.93,25.4 321.31,17.78 313.69,17.78 306.7,10.79 297.81,10.79 297.81,14.61 297.18,15.24 F17.U2 | v220.98,285.12 211.46,275.59 v211.46,273.69 | v204.47,131.44 206.38,129.54 206.38,107.31 203.84,104.77 203.84,102.87 203.2,102.23 203.2,100.96 v208.28,95.88 | v233.04,83.82 232.41,83.18 232.41,73.66 234.95,71.12 234.95,64.13 231.78,60.96 231.78,59.69 v232.41,59.05 | v236.85,40.01 244.47,32.38 244.47,26.67 254,17.14 263.52,17.14 263.52,12.06 266.06,9.52 293.37,9.52 293.37,12.06 F17.V2
  Bottom 0.254: v328.93,25.4 331.47,25.4 F14.R2 | v238.12,320.68 236.85,319.41 234.31,319.41 v230.5,315.6 | v231.78,288.93 229.87,287.02 224.79,287.02 224.16,287.66 223.52,287.66 v220.98,285.12
RUN  (via drill 0.61)
  Top 0.254: v71.75,327.03 69.85,328.93 69.85,375.92 68.58,377.19 A35.M2 | v80.64,382.27 82.55,382.27 82.55,410.85 93.34,421.64 166.37,421.64 v166.37,411.48
  Route2 0.254: v401.95,411.48 432.44,411.48 446.4,397.51 448.94,397.51 A05.E2 | v166.37,411.48 170.81,415.93 193.04,415.93 196.22,419.1 265.43,419.1 266.06,418.47 294,418.47 300.99,411.48 317.5,411.48 318.13,410.85 327.66,410.85 328.3,411.48 330.83,411.48 332.11,410.21 v333.38,410.21
  Route3 0.254: v71.75,327.03 73.03,325.75 73.03,313.69 76.2,310.52 76.2,294 77.47,292.74 B34.T2 | v333.38,410.21 333.38,358.14 334.64,356.87 334.64,347.35 330.2,342.9 330.2,306.71 331.47,305.44 B14.N2
  Bottom 0.254: v333.38,410.21 333.38,412.75 363.22,412.75 363.86,412.12 378.46,412.12 379.1,412.75 397.51,412.75 398.78,411.48 v401.95,411.48 | v80.64,382.27 74.3,382.27 73.66,382.91 68.58,382.91 68.58,378.46 A35.M2
S  (via drill 0.61)
  Top 0.254: v331.47,22.86 331.47,19.69 F14.T2 331.47,18.41 331.47,15.88 327.66,12.06 327.66,11.43 v329.56,9.52 | v336.55,107.31 336.55,100.33 335.28,99.06 E14.P2 | v387.35,27.94 386.08,26.67 386.08,24.13 387.35,22.86 387.35,10.16 v385.44,8.25 | v4.45,325.12 4.45,321.31 B40.H2 | v209.55,281.94 209.55,299.72 208.28,300.99 B24.P2 | v336.55,278.77 336.55,255.91 335.28,254.63 C14.H2 | v292.1,279.4 292.1,385.45 293.37,386.72 A17.J2 | v17.14,311.15 22.23,306.07 v22.23,283.21 | v415.93,203.2 v415.93,193.04 | 330.2,207.01 v332.11,205.1 | 330.2,207.01 330.2,229.87 331.47,231.14 C14.R2 | v331.47,136.53 330.83,137.16 330.83,147.95 330.2,148.59 330.2,207.01
  Route3 0.254: v331.47,22.86 330.2,24.13 330.2,37.46 320.68,46.99 320.68,76.83 321.94,78.1 321.94,83.18 320.68,84.45 320.68,97.79 317.5,100.96 317.5,104.14 v318.77,105.41 | v387.35,27.94 388.62,27.94 390.52,26.03 394.97,26.03 F09.R2 | v385.44,8.25 384.18,9.52 372.75,9.52 372.75,8.89 371.48,7.62 361.31,7.62 360.68,8.25 353.69,8.25 353.69,6.98 351.15,4.44 339.09,4.44 336.55,6.98 329.56,6.98 v329.56,9.52 | v414.02,184.15 415.93,186.06 v415.93,193.04 | C14.R2 332.11,232.41 333.38,233.68 333.38,237.49 336.55,240.66 336.55,249.56 335.28,250.82 335.28,253.36 C14.H2 | v336.55,107.31 336.55,137.16 334.64,139.06 331.47,139.06 v331.47,136.53
  Bottom 0.254: v318.77,105.41 319.4,106.04 327.66,106.04 328.3,106.68 335.92,106.68 v336.55,107.31 | v414.02,184.15 411.48,184.15 D08.H2 | v415.93,193.04 420.37,193.04 D07.D2 | v4.45,325.12 1.91,325.12 1.91,329.56 B40.D2 | v336.55,278.77 335.92,278.13 317.5,278.13 316.23,279.4 v292.1,279.4 253.37,279.4 250.19,282.58 210.19,282.58 v209.55,281.94 206.38,281.94 205.1,280.67 200.03,280.67 198.75,281.94 160.66,281.94 160.02,281.31 58.42,281.31 57.78,280.67 45.72,280.67 45.09,280.04 25.4,280.04 v22.23,283.21 | v17.14,311.15 8.89,319.41 5.71,319.41 5.08,320.04 B40.H2 | v415.93,203.2 414.65,204.47 405.76,204.47 405.13,205.1 v332.11,205.1
SDF0  (via drill 0.61)
  Top 0.254: v294,22.23 303.53,12.7 303.53,6.35 306.07,3.81 321.94,3.81 v321.94,4.44 | v483.24,6.98 504.82,6.98 504.82,46.99 500.38,51.44 500.38,53.34 F01.E2
  Route2 0.254: v203.2,12.06 207.01,8.25 231.78,8.25 234.31,10.79 243.21,10.79 247.01,14.61 251.46,14.61 252.09,13.97 259.08,13.97 262.89,17.78 273.69,17.78 277.5,13.97 278.76,13.97 281.94,17.14 288.29,17.14 293.37,22.23 v294,22.23 | v321.94,4.44 323.85,6.35 342.26,6.35 v342.9,5.71
  Route3 0.254: v203.2,12.06 161.93,53.34 161.93,58.42 139.7,80.64 139.7,105.41 130.18,114.93 130.18,125.09 128.91,126.36 E30.D2 | v376.56,5.71 377.82,4.44 406.4,4.44 408.31,2.54 419.74,2.54 v419.74,4.44
  Bottom 0.254: v342.9,5.71 343.54,5.08 374.01,5.08 375.29,6.35 375.92,6.35 v376.56,5.71 | v419.74,4.44 420.37,5.08 462.28,5.08 464.19,6.98 v483.24,6.98
SDF1  (via drill 0.61)
  Top 0.254: v169.54,107.95 171.45,106.04 171.45,29.84 v179.07,22.23 | v225.43,12.06 225.43,4.44 227.97,1.9 283.85,1.9 283.85,5.08 283.21,5.71 283.21,10.79 v284.48,12.06 | v296.55,12.06 297.81,10.79 297.81,8.25 v301.62,4.44 | v483.24,8.25 501.65,26.67 501.65,45.72 500.38,46.99 F01.H2
  Route2 0.254: v169.54,107.95 161.29,116.2 156.21,116.2 146.69,125.73 137.79,125.73 137.16,125.09 132.72,125.09 132.08,124.46 E30.E2 | v179.07,22.23 180.34,20.95 186.69,20.95 190.5,17.14 200.66,17.14 201.29,17.78 209.55,17.78 216.53,10.79 224.16,10.79 v225.43,12.06 | v284.48,12.06 285.75,10.79 288.93,10.79 290.83,12.7 291.46,12.7 292.74,11.43 295.91,11.43 v296.55,12.06
  Route3 0.254: v301.62,4.44 314.96,4.44 314.96,5.08 320.04,10.16 328.93,10.16 329.56,10.79 335.92,10.79 336.55,10.16 359.41,10.16 359.41,10.79 366.39,17.78 374.65,17.78 374.65,19.69 379.73,24.77 v379.73,25.4 | v387.35,24.77 v408.31,3.81
  Bottom 0.254: v379.73,25.4 380.37,24.77 381,24.77 381.63,24.13 386.71,24.13 v387.35,24.77 | v408.31,3.81 417.83,3.81 419.74,5.71 460.38,5.71 462.28,7.62 482.6,7.62 v483.24,8.25
SDF2  (via drill 0.61)
  Route2 0.254: v427.99,24.13 424.18,20.32 415.29,20.32 414.65,20.95 405.76,20.95 401.95,17.14 399.42,17.14 396.24,20.32 389.89,20.32 389.25,20.95 384.18,20.95 383.54,21.59 381.63,21.59 v379.1,19.05 | v375.92,15.88 375.29,16.51 374.65,16.51 373.38,17.78 365.76,17.78 363.86,15.88 v362.58,15.88 | v334.64,18.41 332.74,20.32 326.39,20.32 325.75,20.95 321.31,20.95 v320.04,22.23 | v255.27,86.99 248.28,93.98 239.4,93.98 235.59,90.17 226.69,90.17 222.88,93.98 215.26,93.98 196.22,113.03 188.59,113.03 182.25,106.68 173.99,106.68 173.35,106.04 164.47,106.04 154.94,115.57 148.59,115.57 147.96,116.2 139.06,116.2 138.43,115.57 135.89,115.57 134.62,116.84 132.08,116.84 E30.H2
  Route3 0.254: v375.92,15.88 v379.1,19.05 | v362.58,15.88 360.68,17.78 351.79,17.78 351.15,17.14 342.26,17.14 341.63,17.78 339.09,17.78 338.45,17.14 334.64,17.14 v334.64,18.41 | v320.04,22.23 320.04,21.59 318.77,20.32 313.69,20.32 304.8,29.21 304.8,43.82 298.45,50.16 298.45,63.5 296.55,65.41 294.64,65.41 286.38,73.66 284.48,73.66 v284.48,83.82
  Bottom 0.254: v427.99,24.13 434.34,24.13 443.87,33.66 452.75,33.66 453.39,33.02 455.93,33.02 456.56,33.66 465.45,33.66 466.09,33.02 468.63,33.02 469.26,33.66 478.15,33.66 478.79,33.02 487.68,33.02 491.49,36.83 495.94,36.83 496.57,37.46 F01.L2 | v284.48,83.82 275.59,83.82 274.95,84.45 266.06,84.45 265.43,83.82 262.89,83.82 262.25,84.45 257.81,84.45 v255.27,86.99
SIF0  (via drill 0.61)
  Top 0.254: v426.72,20.95 431.8,26.03 v431.8,46.99
  Route2 0.254: v201.93,12.06 206.38,7.62 245.75,7.62 v246.38,8.25 | v431.8,46.99 446.4,61.59 454.66,61.59 458.47,65.41 463.55,65.41 495.3,97.16 495.3,107.31 496.57,107.31 E01.L2
  Route3 0.254: v201.93,12.06 193.68,20.32 188.59,20.32 133.35,75.56 133.35,109.22 132.08,110.49 E30.K2 | v347.98,8.25 351.15,8.25 352.43,9.52 361.95,9.52 v361.95,10.79
  Bottom 0.254: v246.38,8.25 260.35,8.25 260.99,8.89 306.7,8.89 307.34,9.52 316.23,9.52 317.5,8.25 332.11,8.25 332.74,8.89 347.35,8.89 v347.98,8.25 | v361.95,10.79 402.59,10.79 408.94,17.14 416.56,17.14 420.37,20.95 v426.72,20.95
SIF1  (via drill 0.61)
  Top 0.254: v365.12,31.75 365.12,24.13 v360.05,19.05
  Route2 0.254: v474.98,75.56 438.79,39.37 427.99,39.37 421.64,45.72 415.29,45.72 414.65,46.36 405.76,46.36 401.95,42.55 400.69,42.55 397.51,45.72 392.43,45.72 389.25,42.55 382.9,42.55 376.56,36.2 370.2,36.2 367.03,33.02 366.39,33.02 v365.12,31.75 | v360.05,19.05 358.77,17.78 351.79,17.78 351.15,17.14 342.26,17.14 341.63,17.78 339.09,17.78 335.28,13.97 326.39,13.97 322.58,17.78 313.69,17.78 313.06,17.14 304.17,17.14 297.18,24.13 288.29,24.13 284.48,20.32 275.59,20.32 274.95,20.95 266.06,20.95 265.43,20.32 262.89,20.32 262.25,20.95 253.37,20.95 249.56,17.14 240.66,17.14 236.85,20.95 227.97,20.95 227.33,20.32 224.79,20.32 220.98,24.13 212.09,24.13 208.28,20.32 201.29,20.32 v199.39,22.23 | v156.84,81.91 134.62,104.14 132.08,104.14 E30.M2
  Route3 0.254: v199.39,22.23 168.28,53.34 168.28,67.94 156.84,79.38 v156.84,81.91
  Bottom 0.254: v474.98,75.56 493.39,93.98 495.94,93.98 496.57,94.61 E01.R2
SIF2  (via drill 0.61)
  Top 0.254: v219.07,27.94 219.07,12.06 210.82,3.81 206.38,3.81 199.39,10.79 v199.39,11.43
  Route2 0.254: v376.56,33.66 375.29,33.66 372.11,30.48 364.49,30.48 363.86,29.84 354.96,29.84 354.33,30.48 351.79,30.48 347.98,26.67 341,26.67 337.19,30.48 328.3,30.48 327.66,29.84 322.58,29.84 321.31,31.12 320.68,31.12 320.04,30.48 313.69,30.48 313.06,29.84 311.15,29.84 309.25,31.75 308.61,31.75 307.34,30.48 300.99,30.48 300.36,29.84 291.46,29.84 290.83,30.48 288.29,30.48 287.65,29.84 283.21,29.84 282.57,29.21 279.4,29.21 278.13,30.48 275.59,30.48 274.95,29.84 272.42,29.84 v271.78,30.48
  Route3 0.254: v477.52,40.64 495.3,58.42 495.3,85.09 499.75,85.09 E01.U2 | v199.39,11.43 198.12,10.16 182.25,10.16 182.25,13.97 127,69.22 127,91.44 131.44,95.88 131.44,97.79 E30.P2
  Bottom 0.254: v477.52,40.64 476.25,39.37 466.09,39.37 465.45,40.01 456.56,40.01 455.93,39.37 453.39,39.37 452.75,40.01 443.87,40.01 440.06,36.2 437.51,36.2 434.34,39.37 427.99,39.37 427.36,40.01 424.81,40.01 421.64,36.83 419.1,36.83 418.46,37.46 415.93,37.46 414.65,36.2 405.76,36.2 401.95,40.01 399.42,40.01 396.24,36.83 391.16,36.83 384.81,30.48 381,30.48 379.73,31.75 378.46,31.75 v376.56,33.66 | v271.78,30.48 269.24,33.02 262.89,33.02 262.25,33.66 260.99,33.66 257.81,30.48 250.19,30.48 247.01,27.3 240.66,27.3 236.85,23.49 235.59,23.49 232.41,26.67 226.69,26.67 225.43,27.94 222.25,27.94 221.62,27.3 219.71,27.3 v219.07,27.94
SKP  (via drill 0.61)
  Top 0.254: v414.65,67.31 419.1,62.87 v419.1,34.92 | v471.17,36.2 473.07,34.29 473.07,24.13 474.35,22.86 F03.S2
  Route3 0.254: v408.31,105.41 409.57,104.14 409.57,72.39 v414.65,67.31
  Bottom 0.254: v408.31,105.41 403.86,109.85 401.32,109.85 400.69,109.22 391.8,109.22 391.16,109.85 388.62,109.85 385.44,106.68 381.63,106.68 381,107.31 377.82,107.31 376.56,106.04 371.48,106.04 370.2,107.31 E11.L2 | v419.1,34.92 420.37,33.66 429.26,33.66 429.89,33.02 438.79,33.02 442.6,36.83 451.49,36.83 452.12,36.2 454.66,36.2 455.3,36.83 464.19,36.83 464.82,36.2 467.36,36.2 468,36.83 470.54,36.83 v471.17,36.2
SP0  (via drill 0.61)
  Top 0.254: F37.H2 43.18,48.26 44.45,49.53 44.45,188.59 43.18,189.86 D37.E2 | v33.66,196.85 31.75,198.75 31.75,245.75 30.48,247.01 C38.K2
  Bottom 0.254: v33.66,196.85 39.37,191.13 42.55,191.13 D37.E2
SP1  (via drill 0.61)
  Top 0.254: v33.66,42.55 34.92,43.82 34.92,161.29 40.01,166.37 40.01,167.64 D37.N2
  Route2 0.254: D37.M2 42.55,170.81 40.64,168.91 40.01,168.91 D37.N2
  Bottom 0.254: v33.66,42.55 30.48,42.55 30.48,46.99 F38.H2
SP2  (via drill 0.61)
  Top 0.254: v36.83,71.12 38.1,72.39 v38.1,104.77
  Route2 0.254: v36.83,71.12 18.41,52.7 17.78,52.7 17.78,48.26 F39.H2
  Route3 0.254: v38.1,104.77 41.27,104.77 41.27,116.84 38.1,120.02 38.1,146.05 39.37,147.32 39.37,148.59 D37.V2
STROBE_EN  (via drill 0.61)
  Top 0.254: E36.K2 55.88,111.76 57.15,113.03 57.15,120.02 55.88,121.28 55.88,123.19 E36.E2 55.88,124.46 57.15,125.73 57.15,138.43 v55.24,138.43
  Route2 0.254: v55.24,138.43 40.01,138.43 20.95,157.48 14.61,157.48 14.61,161.29 D39.R2
STROBE_ENABLE  (via drill 0.61)
  Top 0.254: v125.09,56.52 133.35,64.77 133.35,121.92 v135.25,123.82
  Route3 0.254: v135.25,123.82 136.53,125.09 136.53,161.29 142.88,167.64 142.88,172.72 141.6,173.99 D29.L2
  Bottom 0.254: v125.09,56.52 111.12,42.55 107.31,42.55 106.68,41.91 F32.K2
SX  (via drill 0.61)
  Top 0.254: 219.07,392.43 219.07,398.15 217.81,399.42 A23.D2 | 219.07,392.43 219.07,386.08 220.34,384.81 A23.K2 | B24.D2 205.1,330.84 205.74,331.47 205.74,335.28 206.38,335.92 206.38,391.8 205.1,393.06 A24.F2 | 219.07,392.43 213.36,392.43 v213.36,391.8 | v187.96,278.77 190.5,281.31 190.5,287.02 191.77,288.29 191.77,291.47 B25.T2 | v203.2,311.15 v203.2,293.37
  Route3 0.254: v203.2,311.15 203.2,328.3 204.47,329.56 B24.D2
  Bottom 0.254: v213.36,391.8 210.19,391.8 208.91,393.06 205.1,393.06 A24.F2 | v187.96,278.77 187.32,279.4 163.19,279.4 161.29,277.5 145.41,277.5 144.15,278.77 76.2,278.77 75.56,278.13 55.24,278.13 53.34,276.23 15.88,276.23 15.24,276.86 1.91,276.86 1.91,285.12 B40.V2 | v203.2,293.37 199.39,293.37 198.75,294 193.68,294 192.41,292.74 B25.T2
SY  (via drill 0.61)
  Top 0.254: A23.L2 217.17,380.37 215.9,379.1 v215.9,365.12 v215.9,326.39 | v210.82,290.2 212.72,290.2 212.72,318.77 209.55,321.95 208.28,321.95 208.28,321.31 B24.H2
  Route2 0.254: v215.9,326.39 211.46,321.95 208.91,321.95 208.28,321.31 B24.H2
